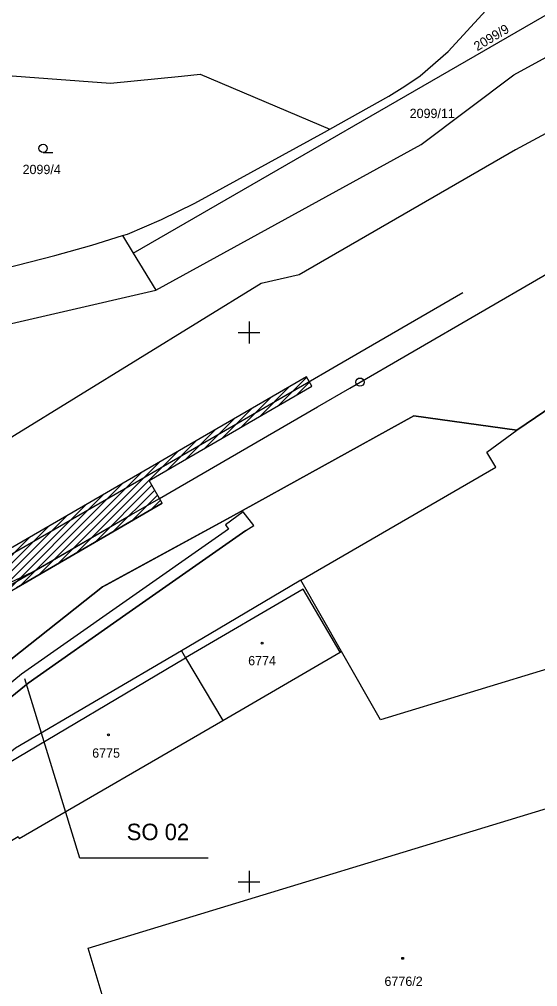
# Model space of a CAD drawing. Extents: x -566165 to -565287, y -1203064 to -1202391.
# Drawn here: x -565741.8 to -565647.5, y -1202819.1 to -1202643 of the extents above; entities that cross this region are included whole.
import ezdxf

# ---------------------------------------------------------------- set-up
doc = ezdxf.new("R2010")
doc.units = 0
for name, color, linetype in [('CD', 7, 'Continuous'), ('Hranice parcel', 7, 'Continuous'), ('Parcelní čísla', 7, 'Continuous'), ('Popis PS SO', 7, 'Continuous'), ('VBř', 7, 'Continuous'), ('Vnitřní kresba', 7, 'Continuous'), ('Vrstva 1', 7, 'Continuous'), ('Vrstva 5', 7, 'Continuous'), ('Vrstva 7', 7, 'Continuous'), ('Značky budov', 7, 'Continuous'), ('Značky kultur', 7, 'Continuous'), ('ČD dotčená část', 7, 'Continuous'), ('ČD pro SŽDC', 7, 'Continuous')]:
    doc.layers.add(name, color=color, linetype=linetype)

msp = doc.modelspace()

# ---------------------------------------------------------------- linework, layer by layer
at = {"layer": 'CD'}
for points in [[(-565834.73, -1202732.72), (-565824.28, -1202726.13), (-565816.76, -1202721.27), (-565816.24, -1202720.98), (-565795.32, -1202709.38), (-565783.5, -1202707.11), (-565769.79, -1202704.47), (-565716.98, -1202692.29), (-565668.65, -1202665.75), (-565651.82, -1202653.08), (-565584.94, -1202616.47), (-565582.08, -1202612.99), (-565579.05, -1202609.31), (-565569.85, -1202598.11), (-565567.82, -1202597.46), (-565565.95, -1202596.85), (-565564.75, -1202597.63), (-565564, -1202597.36)], [(-565608.23, -1202688.5), (-565651.3, -1202717.76), (-565670.03, -1202715.16), (-565703.34, -1202733.61), (-565726.67, -1202746.32), (-565751.56, -1202766.01), (-565767.54, -1202780.11), (-565780.3, -1202792.87), (-565792.68, -1202808.29), (-565796.55, -1202801.32), (-565834.73, -1202732.72), (-565824.28, -1202726.13), (-565816.76, -1202721.27), (-565816.24, -1202720.98), (-565795.32, -1202709.38), (-565783.5, -1202707.11), (-565769.79, -1202704.47), (-565716.98, -1202692.29), (-565668.65, -1202665.75), (-565651.82, -1202653.08), (-565584.94, -1202616.47)], [(-565536.63, -1202645.61), (-565545.69, -1202654.38), (-565570.41, -1202669.07), (-565591.05, -1202679), (-565608.23, -1202688.5), (-565651.3, -1202717.76), (-565670.03, -1202715.16), (-565703.34, -1202733.61), (-565726.67, -1202746.32), (-565751.56, -1202766.01), (-565767.54, -1202780.11)]]:
    msp.add_lwpolyline(points, dxfattribs=at)
at = {"layer": 'Hranice parcel'}
for p, q in [((-565721.08, -1202685.53), (-565588.7, -1202609.16)), ((-565685.27, -1202662.95), (-565674.56, -1202656.97)), ((-565686.26, -1202663.51), (-565685.27, -1202662.95)), ((-565728.61, -1202684.07), (-565723, -1202682.34)), ((-565723, -1202682.34), (-565722.1, -1202682.06)), ((-565723, -1202682.34), (-565721.08, -1202685.53)), ((-565721.08, -1202685.53), (-565716.98, -1202692.29)), ((-565512.6, -1202720.6), (-565676.1, -1202770.5)), ((-565683.18, -1202758.09), (-565690.6, -1202745.1)), ((-565676.1, -1202770.5), (-565683.18, -1202758.09))]:
    msp.add_line(p, q, dxfattribs=at)
for points in [[(-565716.98, -1202692.29), (-565668.65, -1202665.75), (-565651.82, -1202653.08), (-565584.94, -1202616.47)], [(-565674.56, -1202656.97), (-565671.65, -1202655.14), (-565668.84, -1202653.22), (-565663.79, -1202648.82), (-565656.92, -1202641.34)], [(-565752.11, -1202652.57), (-565725.23, -1202654.6), (-565712.28, -1202653.27), (-565708.87, -1202652.92), (-565685.27, -1202662.95)], [(-565722.1, -1202682.06), (-565715.93, -1202679.42), (-565709.88, -1202676.43), (-565686.26, -1202663.51)], [(-565651.3, -1202717.76), (-565608.23, -1202688.5), (-565591.05, -1202679), (-565570.41, -1202669.07)], [(-565779.12, -1202697.06), (-565769.91, -1202694.83), (-565735.3, -1202685.95), (-565728.61, -1202684.07)], [(-565795.32, -1202709.38), (-565783.5, -1202707.11), (-565769.79, -1202704.47), (-565716.98, -1202692.29)], [(-565651.3, -1202717.76), (-565670.03, -1202715.16), (-565703.34, -1202733.61), (-565726.67, -1202746.32), (-565751.56, -1202766.01), (-565767.54, -1202780.11)], [(-565690.6, -1202745.1), (-565655.1, -1202724.5), (-565656.7, -1202721.8), (-565651.3, -1202717.76)], [(-565690.6, -1202745.1), (-565705.63, -1202754.02), (-565712.3, -1202757.94)], [(-565712.3, -1202757.94), (-565742.5, -1202775.71), (-565752.98, -1202784.04)], [(-565712.3, -1202757.94), (-565711.54, -1202759.22), (-565704.78, -1202770.64)], [(-565704.78, -1202770.64), (-565683.41, -1202758.22), (-565683.18, -1202758.09)], [(-565752.98, -1202784.04), (-565746.85, -1202794.61), (-565742.01, -1202791.8), (-565741.8, -1202792.15), (-565704.78, -1202770.64)], [(-565723.1, -1202832.75), (-565729.26, -1202812.13), (-565636.55, -1202783.84), (-565636.4, -1202784.32)]]:
    msp.add_lwpolyline(points, dxfattribs=at)
at = {"layer": 'Popis PS SO'}
msp.add_lwpolyline([(-565707.42, -1202795.71), (-565730.81, -1202795.71), (-565740.81, -1202763.03)], dxfattribs=at)
at = {"layer": 'VBř'}
for points in [[(-565700.6, -1202736.02), (-565699.15, -1202735.14), (-565701.06, -1202732.67), (-565704.26, -1202735.04), (-565703.72, -1202735.77)], [(-565700.6, -1202736.02), (-565699.15, -1202735.14), (-565701.06, -1202732.67), (-565704.26, -1202735.04), (-565703.72, -1202735.77)], [(-565700.6, -1202736.02), (-565722.39, -1202751.33), (-565740.21, -1202763.83), (-565751.17, -1202772.78), (-565763.17, -1202785.08), (-565773.4, -1202795.31)], [(-565773.4, -1202795.31), (-565763.17, -1202785.08), (-565751.17, -1202772.78), (-565740.21, -1202763.83), (-565722.39, -1202751.33), (-565700.6, -1202736.02)], [(-565703.72, -1202735.77), (-565723.54, -1202749.69), (-565741.42, -1202762.23), (-565752.52, -1202771.3), (-565764.59, -1202783.67), (-565773.11, -1202792.19)], [(-565703.72, -1202735.77), (-565723.54, -1202749.69), (-565741.42, -1202762.23), (-565752.52, -1202771.3), (-565764.59, -1202783.67), (-565773.11, -1202792.19)]]:
    msp.add_lwpolyline(points, dxfattribs=at)
at = {"layer": 'Vnitřní kresba'}
for p, q in [((-565690.14, -1202746.71), (-565711.54, -1202759.22)), ((-565683.41, -1202758.22), (-565690.14, -1202746.71)), ((-565748.29, -1202780.97), (-565711.54, -1202759.22))]:
    msp.add_line(p, q, dxfattribs=at)
at = {"layer": 'Vrstva 1'}
for points in [[(-565758.48, -1202754.71), (-565721.48, -1202733.21), (-565716.28, -1202730.2), (-565687.52, -1202713.5), (-565681.68, -1202710.1), (-565634.86, -1202682.91)], [(-565809.14, -1202778.62), (-565772.11, -1202757.13), (-565768.53, -1202755.04), (-565741.86, -1202739.56), (-565718.89, -1202726.24), (-565715.99, -1202724.54), (-565690.27, -1202709.61), (-565684.03, -1202706), (-565661.11, -1202692.68)], [(-565875.64, -1202817.45), (-565857.12, -1202806.56), (-565852.87, -1202804.07), (-565846.29, -1202800.23), (-565828.61, -1202789.92), (-565810.66, -1202779.51), (-565809.41, -1202778.78), (-565809.14, -1202778.62), (-565791.15, -1202768.18), (-565781.12, -1202763.52), (-565771.26, -1202758.74), (-565767.75, -1202757.08), (-565765.33, -1202755.93), (-565759.34, -1202753.1), (-565749.49, -1202748.32), (-565739.46, -1202743.66), (-565721.48, -1202733.21)]]:
    msp.add_lwpolyline(points, dxfattribs=at)
at = {"layer": 'Vrstva 5'}
for p, q in [((-565700, -1202698), (-565700, -1202702)), ((-565702, -1202700), (-565698, -1202700)), ((-565700, -1202798), (-565700, -1202802)), ((-565702, -1202800), (-565698, -1202800))]:
    msp.add_line(p, q, dxfattribs=at)
at = {"layer": 'Vrstva 7'}
msp.add_circle((-565679.81, -1202709.02), 0.75, dxfattribs=at)
at = {"layer": 'Značky budov'}
for centre in [(-565697.63, -1202756.58), (-565725.59, -1202773.26), (-565672.04, -1202813.96)]:
    msp.add_circle(centre, 0.175, dxfattribs=at)
at = {"layer": 'Značky kultur'}
msp.add_line((-565737.47, -1202667.2), (-565735.72, -1202667.2), dxfattribs=at)
msp.add_circle((-565737.47, -1202666.45), 0.75, dxfattribs=at)
at = {"layer": 'ČD dotčená část'}
for p, q in [((-565694.75, -1202713.37), (-565689.5, -1202708.11)), ((-565691.38, -1202711.41), (-565688.98, -1202709)), ((-565698.12, -1202715.33), (-565692.61, -1202709.81)), ((-565701.5, -1202717.28), (-565695.98, -1202711.77)), ((-565704.87, -1202719.24), (-565699.35, -1202713.73)), ((-565708.24, -1202721.2), (-565702.73, -1202715.68)), ((-565711.61, -1202723.16), (-565706.1, -1202717.64)), ((-565714.98, -1202725.11), (-565709.47, -1202719.6)), ((-565731.44, -1202740.15), (-565712.84, -1202721.56)), ((-565734.81, -1202742.11), (-565716.21, -1202723.52)), ((-565738.18, -1202744.07), (-565719.59, -1202725.47)), ((-565741.55, -1202746.03), (-565722.96, -1202727.43)), ((-565728.07, -1202738.2), (-565717.67, -1202727.8)), ((-565744.93, -1202747.98), (-565726.33, -1202729.39)), ((-565724.69, -1202736.24), (-565717.16, -1202728.7)), ((-565721.32, -1202734.28), (-565716.64, -1202729.59)), ((-565748.3, -1202749.94), (-565729.7, -1202731.35)), ((-565717.95, -1202732.32), (-565716.12, -1202730.49)), ((-565751.67, -1202751.9), (-565733.07, -1202733.3)), ((-565755.04, -1202753.86), (-565736.45, -1202735.26)), ((-565758.41, -1202755.82), (-565739.82, -1202737.22))]:
    msp.add_line(p, q, dxfattribs=at)
msp.add_lwpolyline([(-565758.03, -1202755.59), (-565788.22, -1202773.12), (-565775.99, -1202788.56), (-565788.22, -1202773.12), (-565721.02, -1202734.1), (-565715.78, -1202731.06), (-565742.32, -1202746.47), (-565715.78, -1202731.06), (-565718.16, -1202726.96), (-565688.54, -1202709.76), (-565689.54, -1202708.03), (-565745.27, -1202740.39)], dxfattribs=at)
at = {"layer": 'ČD pro SŽDC'}
for points in [[(-565563.53, -1202598.19), (-565564.75, -1202597.63), (-565565.61, -1202597.07), (-565565.95, -1202596.85), (-565566.05, -1202596.88), (-565567.82, -1202597.46), (-565569.85, -1202598.11), (-565579.05, -1202609.31), (-565582.08, -1202612.99), (-565584.94, -1202616.47), (-565578.25, -1202627.55), (-565602.22, -1202640.13), (-565651.5, -1202666.71), (-565690.86, -1202689.45), (-565697.77, -1202691.07), (-565753.97, -1202725.68), (-565774.54, -1202734.62), (-565818.54, -1202761.81)], [(-565563.53, -1202598.19), (-565564.75, -1202597.63), (-565565.61, -1202597.07), (-565565.95, -1202596.85), (-565566.05, -1202596.88), (-565567.82, -1202597.46), (-565569.85, -1202598.11), (-565579.05, -1202609.31), (-565582.08, -1202612.99), (-565584.94, -1202616.47), (-565578.25, -1202627.55), (-565602.22, -1202640.13), (-565651.5, -1202666.71), (-565690.86, -1202689.45), (-565697.77, -1202691.07), (-565753.97, -1202725.68), (-565774.54, -1202734.62), (-565818.54, -1202761.81)], [(-565818.54, -1202761.81), (-565796.55, -1202801.32), (-565767.54, -1202780.11), (-565751.56, -1202766.01), (-565726.67, -1202746.32), (-565725.94, -1202745.92), (-565703.34, -1202733.61), (-565670.03, -1202715.16), (-565651.3, -1202717.76), (-565608.23, -1202688.5), (-565591.05, -1202679), (-565570.41, -1202669.07), (-565545.69, -1202654.38), (-565536.63, -1202645.61)], [(-565818.54, -1202761.81), (-565796.55, -1202801.32), (-565767.54, -1202780.11), (-565751.56, -1202766.01), (-565726.67, -1202746.32), (-565725.94, -1202745.92), (-565703.34, -1202733.61), (-565670.03, -1202715.16), (-565651.3, -1202717.76), (-565608.23, -1202688.5), (-565591.05, -1202679), (-565570.41, -1202669.07), (-565545.69, -1202654.38), (-565536.63, -1202645.61)]]:
    msp.add_lwpolyline(points, dxfattribs=at)

# ---------------------------------------------------------------- texts
at = {"layer": 'Parcelní čísla'}
msp.add_text('2099/9', height=1.7, rotation=31, dxfattribs=at).set_placement((-565658.45, -1202648.77))
for s, p in [('2099/11', (-565670.77, -1202660.93)), ('2099/4', (-565741.2, -1202671.14)), ('6774', (-565700.15, -1202760.59)), ('6775', (-565728.53, -1202777.42)), ('6776/2', (-565675.35, -1202818.99))]:
    msp.add_text(s, height=1.7, dxfattribs=at).set_placement(p)
at = {"layer": 'Popis PS SO'}
msp.add_text('SO 02', height=3, dxfattribs=at).set_placement((-565722.25, -1202792.44))

doc.saveas('drawing.dxf')
